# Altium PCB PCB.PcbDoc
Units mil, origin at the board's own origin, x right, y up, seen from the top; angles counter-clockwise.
Board outline 1000 x 650 mil, 2 copper layers (Top Layer, Bottom Layer), stack 62 mil thick; 20 components, 14 nets, 57 pads, 2 vias.
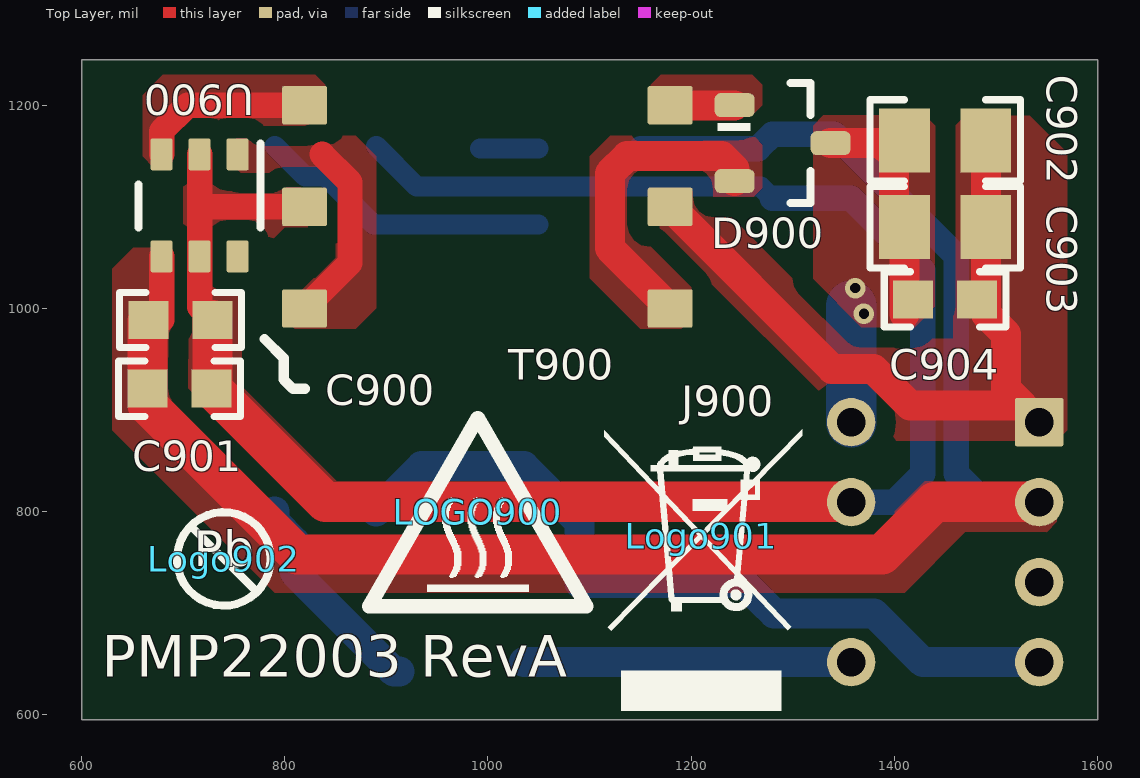
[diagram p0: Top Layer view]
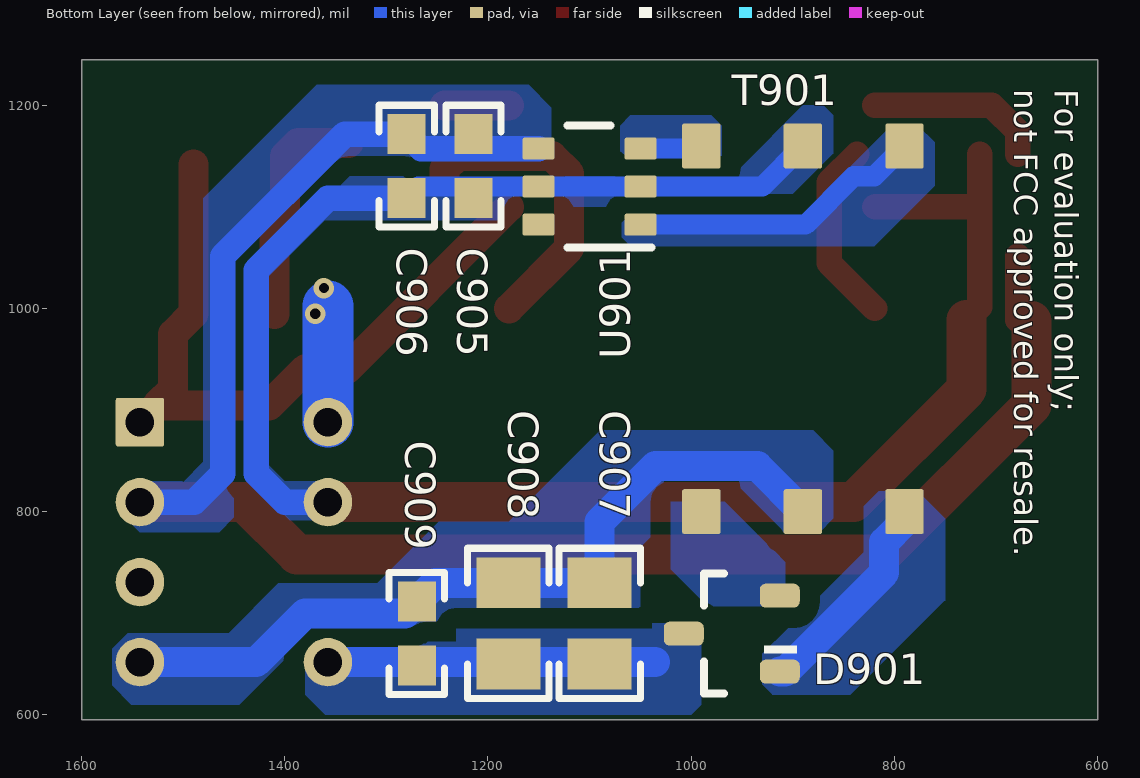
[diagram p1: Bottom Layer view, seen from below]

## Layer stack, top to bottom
Top Solder: solder mask 0.4, Solder Resist, Dk 3.5
Top Layer: signal copper 1.4
Dielectric 2: core 59.2, FR-4, Dk 4.2
Bottom Layer: signal copper 1.4
Bottom Solder: solder mask 0.4, Solder Resist, Dk 3.5

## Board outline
600,595 1600,595 1600,1245 600,1245

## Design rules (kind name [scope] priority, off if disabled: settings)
AcuteAngle [All] p1: minimum=4.50000000000000E+0001 checktracksonly=FALSE
AssemblyTestPointUsage [All] p1: valid=2
Clearance Clearance_2 [InNetClass('HV') vs Not InNetClass('HV')] p1: gap=50 ignorepadtopadclearanceinfootprint=FALSE except(0: Arc-Hole Track-Hole SMDPad-Hole THPad-Hole Via-Hole Fill-Hole Poly-Hole Region-Hole Text-Hole)
Clearance Clearance_1 [InNetClass('MV') vs Not InNetClass('MV')] p2: gap=20 ignorepadtopadclearanceinfootprint=FALSE
Clearance Clearance_Keepouts [((IsTrack Or IsArc) And Not InPoly) And IsFree and IsKeepOut vs ((IsTrack Or IsArc) And Not InPoly) And IsFree and IsKeepOut] p3: gap=0 ignorepadtopadclearanceinfootprint=FALSE
Clearance Clearance_BoardEdge_MountingHoles [OnCopper and InComponentClass('Mounting Holes') vs IsKeepOut] p4: gap=40 ignorepadtopadclearanceinfootprint=FALSE except(0: Arc-Hole Track-Hole SMDPad-Hole THPad-Hole Via-Hole Fill-Hole Poly-Hole Region-Hole Text-Hole)
Clearance Clearance_BoardEdge_Poly [OnCopper and InPoly vs IsKeepOut] p5: gap=25 ignorepadtopadclearanceinfootprint=FALSE except(0: Arc-Hole Track-Hole SMDPad-Hole THPad-Hole Via-Hole Fill-Hole Poly-Hole Region-Hole Text-Hole)
Clearance Clearance_BoardEdge [OnCopper and Not InComponentClass('Logo') and not InComponentClass('FiducialMark') and not InRegion(1000,500,4000,800) and Not IsKeepout vs IsKeepOut] p6: gap=75 ignorepadtopadclearanceinfootprint=FALSE except(0: Arc-Hole Track-Hole SMDPad-Hole THPad-Hole Via-Hole Fill-Hole Poly-Hole Region-Hole Text-Hole)
Clearance Clearance_Poly [InPolygon] p7: gap=20 ignorepadtopadclearanceinfootprint=FALSE except(0: Arc-Hole Track-Hole SMDPad-Hole THPad-Hole Via-Hole Fill-Hole Poly-Hole Region-Hole Text-Hole)
Clearance [All] p8: gap=7.87 ignorepadtopadclearanceinfootprint=FALSE except(0: Arc-Hole Track-Hole SMDPad-Hole THPad-Hole Via-Hole Fill-Hole Poly-Hole Region-Hole Text-Hole)
ComponentClearance ComponentClearance_MountingHoles_FiducialMarks [InComponentClass('Mounting Holes') vs InComponentClass('FiducialMark')] p1: gap=20 collisioncheckmode=3 verticalgap=10 showdistances=FALSE
ComponentClearance ComponentClearance_Shunt [InComponentClass('Header') vs InComponentClass('Shunt')] p2: gap=0 collisioncheckmode=3 verticalgap=0 showdistances=FALSE
ComponentClearance ComponentClearance_Logo [InComponentClass('Logo')] p3: gap=5 collisioncheckmode=3 verticalgap=10 showdistances=FALSE
ComponentClearance ComponentClearance_ScrewToNut [(HasFootprint('NY PMS 440 0025 PH')) vs (HasFootprint('Keystone_1902C'))] p4: gap=20 collisioncheckmode=3 verticalgap=100000 showdistances=FALSE
ComponentClearance ComponentClearance_MountingHoles [InComponentClass('Mounting Holes')] p5: gap=20 collisioncheckmode=3 verticalgap=10 showdistances=FALSE
ComponentClearance ComponentClearance_SmallPassives [HasFootprint('0201*') or HasFootprint('0402*') or HasFootprint('0508') or HasFootprint('0603*') or HasFootprint('0612') or HasFootprint('0805*') or HasFootprint('0815*') or HasFootprint('0830*') or HasFootprint('1206*') or HasFootprint('1210*') or HasFootprint('1808*') or HasFootprint('1812*') or HasFootprint('1825*') or HasFootprint('2010*') or HasFootprint('2220*') or HasFootprint('2225*') or HasFootprint('2512*') or HasFootprint('2728*') or HasFootprint('3518*') vs HasFootprint('0201*') or HasFootprint('0402*') or HasFootprint('0508') or HasFootprint('0603*') or HasFootprint('0612') or HasFootprint('0805*') or HasFootprint('0815*') or HasFootprint('0830*') or HasFootprint('1206*') or HasFootprint('1210*') or HasFootprint('1808*') or HasFootprint('1812*') or HasFootprint('1825*') or HasFootprint('2010*') or HasFootprint('2220*') or HasFootprint('2225*') or HasFootprint('2512*') or HasFootprint('2728*') or HasFootprint('3518*')] p6: gap=20 collisioncheckmode=3 verticalgap=20 showdistances=FALSE
ComponentClearance ComponentClearance_THtoSMT [IsThruComponent vs IsSMTComponent] p7: gap=10 collisioncheckmode=3 verticalgap=10 showdistances=FALSE
ComponentClearance ComponentClearance_THtoTH [IsThruComponent vs IsThruComponent] p8: gap=10 collisioncheckmode=3 verticalgap=10 showdistances=FALSE
ComponentClearance [All] p9: gap=10 collisioncheckmode=3 verticalgap=10 showdistances=FALSE
DiffPairsRouting [All] p1: maxlimit=100 minlimit=10 mostfreqgap=10 toplayer_minwidth=15 toplayer_maxwidth=15 toplayer_prefwidth=15 bottomlayer_minwidth=15 bottomlayer_maxwidth=15 bottomlayer_prefwidth=15 maxuncoupledlength=1000
FabricationTestPointUsage TestPointUsage [All] p1: valid=2 allowmultiple=FALSE
FabricationTestpoint Testpoint [All] p1: side=3 testpointundercomponent=TRUE minsize=40 maxsize=100 preferedsize=60 minholesize=0 maxholesize=40 preferedholesize=32 testpointgrid=1 allowsidetop=TRUE allowsidebottom=TRUE usegrid=TRUE gridtolerance=0.01
FanoutControl Fanout_LCC [IsLCC] p1: bgadir=Out bgaviamode=Centered fanoutstyle=Auto fanoutdirection=Alternating viagrid=1 // Fanout_LCC (Default Rule)
FanoutControl Fanout_BGA [IsBGA] p2: bgadir=Out bgaviamode=Centered fanoutstyle=Auto fanoutdirection=Alternating viagrid=1 // Fanout_BGA (Default Rule)
FanoutControl Fanout_Default [All] p4: bgadir=Out bgaviamode=Centered fanoutstyle=Auto fanoutdirection=Alternating viagrid=1 // Fanout_Default (Default Rule)
FanoutControl Fanout_Small [(CompPinCount < 5)] p5: bgadir=Out bgaviamode=Centered fanoutstyle=Auto fanoutdirection=OutThenIn viagrid=1 // Fanout_Small (Default Rule)
Height [All] p1: minheight=0 maxheight=3000 prefheight=500
HoleSize [All] p1: absolutevalues=TRUE maxlimit=251 minlimit=7 maxpercent=80.000 minpercent=20.000
MinimumAnnularRing MinimumAnnularRing_ThermalPadVias [IsVia and InAnyComponent] p1: minimumring=5.91
MinimumAnnularRing [All] p2: minimumring=4.9
MinimumSolderMaskSliver MinimumSolderMaskSliver_Logo [InComponentClass('Logo') vs InComponentClass('Logo')] p1: minsoldermaskwidth=0.7
MinimumSolderMaskSliver [All] p2: minsoldermaskwidth=2
PlaneConnect [All] p1: planeconnectstyle=Direct reliefexpansion=10 reliefentries=4 reliefconductorwidth=10 reliefairgap=10
PolygonConnect PolygonConnect_22 [All vs IsNamedPolygon('GND') Or  IsNamedPolygon('T901_1') Or  IsNamedPolygon('D901_1') Or  IsNamedPolygon('+VB') Or  IsNamedPolygon('T900_1') Or  IsNamedPolygon('-VB') Or  IsNamedPolygon('D900_2') Or  IsNamedPolygon('5V') Or  IsNamedPolygon('T901_3') Or  IsNamedPolygon('GND') Or  IsNamedPolygon('-VA') Or  IsNamedPolygon('D900_1') Or  IsNamedPolygon('5V') Or  IsNamedPolygon('T900_3') Or  IsNamedPolygon('D901_1') Or  IsNamedPolygon('+VA')] p1: connectstyle=Direct reliefconductorwidth=10 reliefentries=4 polygonreliefangle="90 Angle" airgapwidth=10
PolygonConnect PolygonConnect_21 [All vs IsNamedPolygon('GND') Or  IsNamedPolygon('+VA') Or  IsNamedPolygon('GND') Or  IsNamedPolygon('T900_3') Or  IsNamedPolygon('-VA') Or  IsNamedPolygon('D900_1') Or  IsNamedPolygon('D900_2') Or  IsNamedPolygon('5V') Or  IsNamedPolygon('T900_1') Or  IsNamedPolygon('5V')] p2: connectstyle=Direct reliefconductorwidth=10 reliefentries=4 polygonreliefangle="90 Angle" airgapwidth=10
PolygonConnect PolygonConnect_20 [All vs IsNamedPolygon('GND') Or  IsNamedPolygon('D900_1') Or  IsNamedPolygon('D900_2') Or  IsNamedPolygon('+VA') Or  IsNamedPolygon('-VA') Or  IsNamedPolygon('T900_1') Or  IsNamedPolygon('T900_3') Or  IsNamedPolygon('5V')] p3: connectstyle=Direct reliefconductorwidth=10 reliefentries=4 polygonreliefangle="90 Angle" airgapwidth=10
PolygonConnect PolygonConnect_19 [All vs IsNamedPolygon('GND') Or  IsNamedPolygon('T900_3') Or  IsNamedPolygon('T900_1') Or  IsNamedPolygon('5V')] p4: connectstyle=Direct reliefconductorwidth=10 reliefentries=4 polygonreliefangle="90 Angle" airgapwidth=10
PolygonConnect PolygonConnect_18 [All vs IsNamedPolygon('T900_1') Or  IsNamedPolygon('T900_3')] p5: connectstyle=Direct reliefconductorwidth=10 reliefentries=4 polygonreliefangle="90 Angle" airgapwidth=10
PolygonConnect PolygonConnect_17 [All vs IsNamedPolygon('4Vb') Or  IsNamedPolygon('4Va') Or  IsNamedPolygon('Comb') Or  IsNamedPolygon('PGND') Or  IsNamedPolygon('5Vp') Or  IsNamedPolygon('Comb') Or  IsNamedPolygon('Coma') Or  IsNamedPolygon('4Vb') Or  IsNamedPolygon('15Vb') Or  IsNamedPolygon('Coma') Or  IsNamedPolygon('15Va') Or  IsNamedPolygon('Comb') Or  IsNamedPolygon('Coma') Or  IsNamedPolygon('Comb') Or  IsNamedPolygon('4Vb') Or  IsNamedPolygon('15Vb') Or  IsNamedPolygon('15Va') Or  IsNamedPolygon('4Vb') Or  IsNamedPolygon('Coma') Or  IsNamedPolygon('4Va') Or  IsNamedPolygon('4Va') Or  IsNamedPolygon('4Va')] p6: connectstyle=Direct reliefconductorwidth=10 reliefentries=4 polygonreliefangle="90 Angle" airgapwidth=10
PolygonConnect PolygonConnect_16 [All vs IsNamedPolygon('15Va') Or  IsNamedPolygon('Coma') Or  IsNamedPolygon('4Vb') Or  IsNamedPolygon('Comb') Or  IsNamedPolygon('PGND') Or  IsNamedPolygon('15Vb') Or  IsNamedPolygon('4Va') Or  IsNamedPolygon('5Vp')] p7: connectstyle=Direct reliefconductorwidth=10 reliefentries=4 polygonreliefangle="90 Angle" airgapwidth=10
PolygonConnect PolygonConnect_15 [All vs IsNamedPolygon('C109_2') Or  IsNamedPolygon('C107_2') Or  IsNamedPolygon('HV') Or  IsNamedPolygon('Q203_5') Or  IsNamedPolygon('C107_2') Or  IsNamedPolygon('HS') Or  IsNamedPolygon('Q201_5') Or  IsNamedPolygon('Q203_5') Or  IsNamedPolygon('C106_2') Or  IsNamedPolygon('C108_2') Or  IsNamedPolygon('Vout') Or  IsNamedPolygon('Q203_5') Or  IsNamedPolygon('C108_2') Or  IsNamedPolygon('C113_2') Or  IsNamedPolygon('Q203_5') Or  IsNamedPolygon('Q201_5') Or  IsNamedPolygon('C107_2') Or  IsNamedPolygon('C102_1') Or  IsNamedPolygon('SGND') Or  IsNamedPolygon('GND') Or  IsNamedPolygon('SGND') Or  IsNamedPolygon('GND') Or  IsNamedPolygon('IN+') Or  IsNamedPolygon('IN+') Or  IsNamedPolygon('Q201_5') Or  IsNamedPolygon('Q201_5') Or  IsNamedPolygon('SGND') Or  IsNamedPolygon('SGND') Or  IsNamedPolygon('Vout') Or  IsNamedPolygon('Vout') Or  IsNamedPolygon('IN+') Or  IsNamedPolygon('GND') Or  IsNamedPolygon('IN+') Or  IsNamedPolygon('GND')] p8: connectstyle=Direct reliefconductorwidth=10 reliefentries=4 polygonreliefangle="90 Angle" airgapwidth=10
PolygonConnect PolygonConnect_14 [All vs IsNamedPolygon('C106_2') Or  IsNamedPolygon('C107_2') Or  IsNamedPolygon('C107_2') Or  IsNamedPolygon('C107_2') Or  IsNamedPolygon('C102_1') Or  IsNamedPolygon('Q203_5') Or  IsNamedPolygon('Vout') Or  IsNamedPolygon('Q203_5') Or  IsNamedPolygon('Q203_5') Or  IsNamedPolygon('Q201_5') Or  IsNamedPolygon('C108_2') Or  IsNamedPolygon('Q203_5') Or  IsNamedPolygon('HS') Or  IsNamedPolygon('HV') Or  IsNamedPolygon('C108_2') Or  IsNamedPolygon('Q201_5') Or  IsNamedPolygon('C109_2') Or  IsNamedPolygon('Q201_5') Or  IsNamedPolygon('Q201_5') Or  IsNamedPolygon('C113_2')] p9: connectstyle=Direct reliefconductorwidth=10 reliefentries=4 polygonreliefangle="90 Angle" airgapwidth=10
PolygonConnect PolygonConnect_13 [All vs IsNamedPolygon('C102_1') Or  IsNamedPolygon('HV') Or  IsNamedPolygon('C107_2') Or  IsNamedPolygon('C109_2') Or  IsNamedPolygon('C107_2') Or  IsNamedPolygon('C108_2') Or  IsNamedPolygon('C106_2') Or  IsNamedPolygon('C108_2') Or  IsNamedPolygon('C113_2') Or  IsNamedPolygon('C107_2')] p10: connectstyle=Direct reliefconductorwidth=10 reliefentries=4 polygonreliefangle="90 Angle" airgapwidth=10
PolygonConnect PolygonConnect_12 [All vs IsNamedPolygon('C107_2') Or  IsNamedPolygon('C113_2') Or  IsNamedPolygon('C106_2') Or  IsNamedPolygon('C107_2') Or  IsNamedPolygon('C107_2') Or  IsNamedPolygon('C102_1')] p11: connectstyle=Direct reliefconductorwidth=10 reliefentries=4 polygonreliefangle="90 Angle" airgapwidth=10
PolygonConnect PolygonConnect_11 [All vs IsNamedPolygon('C106_2') Or  IsNamedPolygon('C102_1') Or  IsNamedPolygon('C107_2') Or  IsNamedPolygon('C107_2') Or  IsNamedPolygon('C107_2')] p12: connectstyle=Direct reliefconductorwidth=10 reliefentries=4 polygonreliefangle="90 Angle" airgapwidth=10
PolygonConnect PolygonConnect_10 [All vs IsNamedPolygon('C106_2')] p13: connectstyle=Direct reliefconductorwidth=10 reliefentries=4 polygonreliefangle="90 Angle" airgapwidth=10
PolygonConnect PolygonConnect_9 [All vs IsNamedPolygon('C11_1') Or  IsNamedPolygon('Vin') Or  IsNamedPolygon('Vin') Or  IsNamedPolygon('5V') Or  IsNamedPolygon('D6_2') Or  IsNamedPolygon('Q3_3') Or  IsNamedPolygon('GND2') Or  IsNamedPolygon('GND2') Or  IsNamedPolygon('GND') Or  IsNamedPolygon('Q3_4') Or  IsNamedPolygon('12V5') Or  IsNamedPolygon('GND') Or  IsNamedPolygon('12V5') Or  IsNamedPolygon('D3_1')] p14: connectstyle=Direct reliefconductorwidth=10 reliefentries=4 polygonreliefangle="90 Angle" airgapwidth=10
PolygonConnect PolygonConnect_8 [All vs IsNamedPolygon('C11_1') Or  IsNamedPolygon('Vin') Or  IsNamedPolygon('12V5') Or  IsNamedPolygon('Q3_3') Or  IsNamedPolygon('GND2') Or  IsNamedPolygon('GND2') Or  IsNamedPolygon('5V') Or  IsNamedPolygon('Q3_4') Or  IsNamedPolygon('12V5')] p15: connectstyle=Direct reliefconductorwidth=10 reliefentries=4 polygonreliefangle="90 Angle" airgapwidth=10
PolygonConnect PolygonConnect_7 [All vs IsNamedPolygon('GND2') Or  IsNamedPolygon('GND2') Or  IsNamedPolygon('5V') Or  IsNamedPolygon('12V5') Or  IsNamedPolygon('12V5') Or  IsNamedPolygon('C11_1')] p16: connectstyle=Direct reliefconductorwidth=10 reliefentries=4 polygonreliefangle="90 Angle" airgapwidth=10
PolygonConnect PolygonConnect_6 [All vs IsNamedPolygon('GND2') Or  IsNamedPolygon('SGND') Or  IsNamedPolygon('GND1') Or  IsNamedPolygon('C901_1') Or  IsNamedPolygon('SGND') Or  IsNamedPolygon('GND2') Or  IsNamedPolygon('GND1')] p17: connectstyle=Direct reliefconductorwidth=10 reliefentries=4 polygonreliefangle="90 Angle" airgapwidth=10
PolygonConnect PolygonConnect_5 [All vs IsNamedPolygon('GND1') Or  IsNamedPolygon('GND1')] p18: connectstyle=Direct reliefconductorwidth=10 reliefentries=4 polygonreliefangle="90 Angle" airgapwidth=10
PolygonConnect PolygonConnect_4 [All vs IsNamedPolygon('C21_1') Or  IsNamedPolygon('C5_1') Or  IsNamedPolygon('C12_2') Or  IsNamedPolygon('C2_2') Or  IsNamedPolygon('C13_1') Or  IsNamedPolygon('C28_1') Or  IsNamedPolygon('C6_1') Or  IsNamedPolygon('GND') Or  IsNamedPolygon('GND2') Or  IsNamedPolygon('C14_1') Or  IsNamedPolygon('C13_1') Or  IsNamedPolygon('Q1_3') Or  IsNamedPolygon('C14_1') Or  IsNamedPolygon('C5_1') Or  IsNamedPolygon('GND2') Or  IsNamedPolygon('C28_1') Or  IsNamedPolygon('D5_2') Or  IsNamedPolygon('D6_2') Or  IsNamedPolygon('D2_1') Or  IsNamedPolygon('C12_2') Or  IsNamedPolygon('D2_1') Or  IsNamedPolygon('C4_1') Or  IsNamedPolygon('C4_1') Or  IsNamedPolygon('C2_2') Or  IsNamedPolygon('GND') Or  IsNamedPolygon('C33_1') Or  IsNamedPolygon('C9_1')] p19: connectstyle=Direct reliefconductorwidth=10 reliefentries=4 polygonreliefangle="90 Angle" airgapwidth=10
PolygonConnect PolygonConnect_3 [All vs IsNamedPolygon('C28_1') Or  IsNamedPolygon('C12_2') Or  IsNamedPolygon('C28_1') Or  IsNamedPolygon('C9_1') Or  IsNamedPolygon('D5_2') Or  IsNamedPolygon('C12_2') Or  IsNamedPolygon('C2_2') Or  IsNamedPolygon('C14_1') Or  IsNamedPolygon('C4_1') Or  IsNamedPolygon('C14_1') Or  IsNamedPolygon('D6_2') Or  IsNamedPolygon('GND2') Or  IsNamedPolygon('Q1_3') Or  IsNamedPolygon('C5_1') Or  IsNamedPolygon('D2_1') Or  IsNamedPolygon('C4_1') Or  IsNamedPolygon('C13_1') Or  IsNamedPolygon('C5_1') Or  IsNamedPolygon('C13_1') Or  IsNamedPolygon('C33_1') Or  IsNamedPolygon('D2_1') Or  IsNamedPolygon('GND') Or  IsNamedPolygon('GND') Or  IsNamedPolygon('GND2') Or  IsNamedPolygon('C2_2') Or  IsNamedPolygon('C6_1') Or  IsNamedPolygon('C21_1')] p20: connectstyle=Direct reliefconductorwidth=10 reliefentries=4 polygonreliefangle="90 Angle" airgapwidth=10
PolygonConnect PolygonConnect_2 [All vs IsNamedPolygon('C21_1') Or  IsNamedPolygon('C4_1') Or  IsNamedPolygon('D5_2') Or  IsNamedPolygon('C5_1') Or  IsNamedPolygon('C14_1') Or  IsNamedPolygon('C13_1') Or  IsNamedPolygon('C4_1') Or  IsNamedPolygon('C33_1') Or  IsNamedPolygon('C12_2') Or  IsNamedPolygon('D2_1') Or  IsNamedPolygon('C2_2') Or  IsNamedPolygon('C28_1') Or  IsNamedPolygon('C12_2') Or  IsNamedPolygon('D2_1') Or  IsNamedPolygon('C5_1') Or  IsNamedPolygon('Q1_3') Or  IsNamedPolygon('GND') Or  IsNamedPolygon('D6_2') Or  IsNamedPolygon('C6_1') Or  IsNamedPolygon('C2_2') Or  IsNamedPolygon('C14_1') Or  IsNamedPolygon('C28_1') Or  IsNamedPolygon('C13_1') Or  IsNamedPolygon('C9_1') Or  IsNamedPolygon('GND')] p21: connectstyle=Direct reliefconductorwidth=10 reliefentries=4 polygonreliefangle="90 Angle" airgapwidth=10
PolygonConnect PolygonConnect_1 [All vs IsNamedPolygon('C28_1') Or  IsNamedPolygon('D5_2') Or  IsNamedPolygon('C5_1') Or  IsNamedPolygon('C5_1') Or  IsNamedPolygon('D2_1') Or  IsNamedPolygon('C21_1') Or  IsNamedPolygon('C9_1') Or  IsNamedPolygon('C4_1') Or  IsNamedPolygon('C14_1') Or  IsNamedPolygon('C28_1') Or  IsNamedPolygon('C6_1') Or  IsNamedPolygon('C12_2') Or  IsNamedPolygon('C33_1') Or  IsNamedPolygon('C4_1') Or  IsNamedPolygon('C13_1') Or  IsNamedPolygon('C12_2') Or  IsNamedPolygon('D6_2') Or  IsNamedPolygon('C2_2') Or  IsNamedPolygon('C14_1') Or  IsNamedPolygon('D2_1') Or  IsNamedPolygon('C2_2') Or  IsNamedPolygon('C13_1')] p22: connectstyle=Direct reliefconductorwidth=10 reliefentries=4 polygonreliefangle="90 Angle" airgapwidth=10
PolygonConnect [All] p23: connectstyle=Relief reliefconductorwidth=10 reliefentries=4 polygonreliefangle="90 Angle" airgapwidth=10
RoutingVias ThermalPadVias [IsVia and InAnyComponent] p1: holewidth=7.87 width=19.68 viastyle="Through Hole" minholewidth=7.87 minwidth=19.68 maxholewidth=12.99 maxwidth=23.62
RoutingVias [All] p2: holewidth=16 width=34 viastyle="Through Hole" minholewidth=7.87 minwidth=20 maxholewidth=40 maxwidth=65
SilkToBoardRegionClearance [Not ((IsComment or IsDesignator) And (Hide <> 'False')) and not InRegion(1000,500,4000,800)] p1:
SilkToSilkClearance SilkToSilkClearance_Pb-FreeLogo [(HasFootprint('Pb-Free_Overlay_Medium') OR HasFootprint('Pb-Free_Overlay_Small')) vs (HasFootprint('Pb-Free_Overlay_Medium') OR HasFootprint('Pb-Free_Overlay_Small'))] p1: silktosilkclearance=0
SilkToSilkClearance [All] p2: silktosilkclearance=1
SilkToSolderMaskClearance "Silk to Solder Mask Opening" [All] p1: minsilkscreentomaskgap=1 clearancetoexposedcopper=FALSE
SolderMaskExpansion [All] p1: expansion=1.97
Width [All] p1: maxlimit=100 minlimit=6 preferedwidth=10 checkconnectedcopper=TRUE
14 further rules are at their usual default settings.

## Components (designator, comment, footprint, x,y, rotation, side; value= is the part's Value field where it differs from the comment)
C900 "C1608X6S1A106M080AC" 0603 697.45,988.7 r180 top value=10uF
C901 "CGA3E2X7R1E104K080AA" 0603 696.46,921 r180 top value=0.1uF
C902 "CGA4J3X5R1H475K125AB" 0805_HV 1450,1165.49 r0 top value=4.7uF
C903 "CGA4J3X5R1H475K125AB" 0805_HV 1450,1080 r0 top value=4.7uF
C904 "CGA3E2X7R1E104K080AA" 0603 1450,1008.88 r0 top value=0.1uF
C905 "C1608X6S1A106M080AC" 0603 1214.21,1140 r90 bottom value=10uF
C906 "CGA3E2X7R1E104K080AA" 0603 1280,1140 r90 bottom value=0.1uF
C907 "CGA4J3X5R1H475K125AB" 0805_HV 1090,690 r90 bottom value=4.7uF
C908 "CGA4J3X5R1H475K125AB" 0805_HV 1180,690 r90 bottom value=4.7uF
C909 "CGA3E2X7R1E104K080AA" 0603 1270,680 r90 bottom value=0.1uF
D900 "BAV70-E3-08" SOT-23 1290,1162.8 r0 top value=70V
D901 "BAV70-E3-08" SOT-23 960,680 r0 bottom value=70V
J900 "MMS-104-01-F-DH" FP-MMS-104-01-F-DH_HDR8-MFG 1450,770 r90 top
LOGO900 "CAUTION HOT SURFACE" IEC_HotSurface_Small 990,800 r0 top
Logo901 "WEEE logo" WEEE_Minimum 1210,776.5 r0 top
Logo902 "Pb-Free Symbol" Pb-Free_Overlay_Small 740,753.5 r0 top
T900 "750317722" Wurth_750317722 999.37,1100 r0 top
T901 "750317722" Wurth_750317722 890,980 r270 bottom
U900 "SN6505BDBVR" DBV0006A_L 716.15,1101.5 r270 top
U901 "SN6505BDBVR" DBV0006A_L 1100,1120 r0 bottom

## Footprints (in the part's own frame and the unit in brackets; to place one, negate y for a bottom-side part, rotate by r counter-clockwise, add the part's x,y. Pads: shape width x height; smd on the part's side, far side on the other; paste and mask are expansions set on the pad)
0603 [mm] "0603 from SM-752 data"
  rect 1x0.95 smd: 1(-0.8,0) 2(0.8,0)
  silkscreen extent -1.52,-0.69 1.52,0.69, body extent -0.87,-0.47 0.87,0.47, height 1
0805_HV [mil] "0805 with 30mil clearance between pads"
  rect 50x63 smd: 1(-40,0) 2(40,0)
  silkscreen extent -74,-40 74,40, body extent -43,-29 43,29, height 57
DBV0006A_L [mm] "SOT23, 6-Leads, Body 2.9x1.6mm, Pitch 0.95mm, Lead Span 2.8mm, IPC High Density"
  rrect18% 0.8x0.55 smd: 1(-1.275,0.95) 2(-1.275,0) 3(-1.275,-0.95) 4(1.275,-0.95) 5(1.275,0) 6(1.275,0.95)
  silkscreen extent -1.55,-1.53 0.55,1.53, body extent -1.42,-1.46 1.42,1.46, height 1.12
FP-MMS-104-01-F-DH_HDR8-MFG [mm]
  rrect8% 1.211x1.211 hole 0.711 paste-1000 mask+0: 1(3,-2.35)
  round 1.211 hole 0.711 paste-1000 mask+0: 2(3,2.35) 3(1,-2.35) 4(1,2.35) 5(-1,-2.35) 7(-3,-2.35) 8(-3,2.35)
  body extent -4.44,-3.06 4.44,3.06, height 0.25
IEC_HotSurface_Small [mil]
  silkscreen extent -107,-93 107,92
Pb-Free_Overlay_Small [mil]
  silkscreen extent -46,-46 46,46
SOT-23 [mm] "SOT23, 3-Leads, Body 2.9x1.3mm, Pitch 0.95mm, Lead Span 2.5mm, IPC Medium Density"
  rrect50% 1x0.6 smd: 1(-1.2,0.95) 2(-1.2,-0.95) 3(1.2,0)
  silkscreen extent -1.63,-1.5 0.7,1.5, body extent -1.16,-1.45 1.21,1.45, height 1
WEEE_Minimum [mil] "WEEElie bin"
  silkscreen extent -95,-172 99,104
Wurth_750317722 [mm] "SMD, 6-Leads, Body 7.14x6.73mm, Pitch 2.54mm"
  rrect10% 1.12x0.96 smd: 1(-4.57,2.54) 2(-4.57,0) 3(-4.57,-2.54) 4(4.57,-2.54) 5(4.57,0) 6(4.57,2.54)
  body extent -5.23,-3.36 5.23,3.37, height 4.19

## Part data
C900 C905: library part GRT188C81A106ME13D, "CAP, CERM, 10 µF, 10 V,+/- 20%, X6S, AEC-Q200 Grade 2, 0603", Cap_Case=0603, Manufacturer=TDK, TempCo=X6S, Tolerance_%=20, Value2=10V, ValueDisplayed=10µF
C901 C904 C906 C909: "CAP, CERM, 0.1 µF, 25 V,+/- 10%, X7R, AEC-Q200 Grade 1, 0603", Cap_Case=0603, Manufacturer=TDK, Supplier Part Number 1=445-5667-1-ND, TempCo=X7R, Tolerance_%=10, Value2=25V, ValueDisplayed=0.1µF
C902 C903 C907 C908: library part GRT21BR61H475KE13L, "CAP, CERM, 4.7 µF, 50 V,+/- 10%, X5R, AEC-Q200 Grade 3, 0805", Cap_Case=0805, Manufacturer=TDK, TempCo=X5R, Tolerance_%=10, Value2=50V, ValueDisplayed=4.7µF
D900 D901: "Diode, Switching, 70 V, 0.25 A, AEC-Q101, SOT-23", Manufacturer=Vishay-Semiconductor, Supplier Part Number 1=BAV70-E3-08CT-ND, Value1=0.25A, Value2=1.25V
J900: library part CMP-0087213-1, "8 Position Receptacle Connector Through Hole, Right Angle", Current_A=3.9A, Manufacturer=Samtec, Voltage_V=350V
LOGO900: library part IEC_HotSurface, "IEC 61010-1 Hot Surface Warning"
Logo901: library part CMP-0074769-1
Logo902: library part CMP-0074839-1
T900 T901: library part CMP-0081994-1, "Transformer, 320 uH, SMD", Manufacturer="Wurth Elektronik"
U900 U901: library part CMP-0076095-1, "Low-Noise 1 A, 420 kHz Transformer Driver, DBV0006A (SOT-23-6)", Alternate Manufacturer="Texas Instruments", Alternate PartNumber=SN6505BDBVT

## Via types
v1: diameter 20, hole 10, Top Layer to Bottom Layer, 2 vias

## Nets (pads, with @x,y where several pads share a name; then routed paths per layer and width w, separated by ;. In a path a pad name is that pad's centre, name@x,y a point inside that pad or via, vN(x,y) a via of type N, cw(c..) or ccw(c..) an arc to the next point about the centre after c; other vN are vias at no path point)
5V: C900.1 C901.1 C905.1 C906.1 J900.4 T900.2 T901.2 U900.2 U900.5 U901.2 U901.5 | length 1884.1
  Top Layer w25: U900.2 U900.5 716.15,1001.5 C900.1 ; 717.64,1100 T900.2
  Top Layer w39.37: C900.1 728.94,920.62 840.2,809.37 J900.4
  Bottom Layer w20: T901.2 929.92,1120 U901.2 U901.5 1268.5,1120 C906.1
  Bottom Layer w25: C906.1 1357.5,1108.5 1428.11,1037.89 1428.11,837.48 1400,809.37 J900.4
+VA: C902.1 C903.1 C904.1 D900.3 J900.2 | length 341.8
  Top Layer w29.53: D900.3 1387.21,1162.8 1399.81,1150.21 1399.81,1090.19 C903.1 C904.1@1410,994.8
  Bottom Layer w50: J900.2 1357.48,1002.52
  other v1: 1370,994.8 1361.5,1020
+VB: C907.1 C908.1 C909.1 D901.3 J900.8 | length 322.1
  Bottom Layer w29.53: 1035.35,651.89 J900.8
-VA: C902.2 C903.2 C904.2 J900.1 T900.5 | length 679.5
  Top Layer w29.53: T900.5 1338.63,940.67 1379.33,940.67 1415.32,904.68 1525.95,904.68 1510,920.63 1510,974.8 1490,994.8 C903.2 C902.2@1490,1141.7
-VB: C907.2 C908.2 C909.2 J900.7 T901.5 | length 786.1
  Bottom Layer w29.53: T901.5 934.69,844.76 1035.24,844.76 1090,790 C907.2 C908.2 1251.5,730 C909.2 1281.5,700 1380,700 1428.11,651.89 J900.7
GND: C900.2 C901.2 C905.2 C906.2 J900.3 U900.4 U901.4 | length 1779.6
  Top Layer w25: C900.2@665.95,987.72 C900.2 ; C900.2@678.75,988.7 U900.4
  Top Layer w39.37: C900.2@664.97,987.72 C901.2 664.97,905.03 812.03,757.97 1387.97,757.97 1439.37,809.37 J900.3
  Bottom Layer w25: U901.4 1265.91,1157.4 C906.2 1340.99,1171.5 1460.98,1051.51 1460.98,837.48 1489.09,809.37 J900.3
NetD900_1: D900.1 T900.6 | length 63.3
  Top Layer w29.53: T900.6 D900.1@1242.55,1200
NetD900_2: D900.2 T900.4 | length 304.5
  Top Layer w29.53: T900.4 1120,1059.29 1120,1132.99 1137.01,1150 1230,1150 1242.76,1137.24 D900.2
NetD901_1: D901.1 T901.6 | length 211.5
  Bottom Layer w29.53: T901.6 790,790 810,770 810,740 907.4,642.6 D901.1
NetD901_2: D901.2 T901.4
NetT900_1: T900.1 U900.3 | length 174.1
  Top Layer w25: U900.3 678.75,1174.49 704.25,1200 T900.1
NetT900_3: T900.3 U900.1 | length 181.6
  Top Layer w25: T900.3 864.25,1044.8 864.25,1124.19 836.75,1151.69
NetT901_1: T901.1 U901.1 | length 291.8
  Bottom Layer w20: T901.1 819.92,1130 840,1130 887.4,1082.6 U901.1
NetT901_3: T901.3 U901.3 | length 57.3
  Bottom Layer w20: T901.3@992.52,1157.4 U901.3
pads on no net: J900.5 U900.6 U901.6

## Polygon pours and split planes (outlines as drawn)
NetT900_1 on Top Layer "T900_1" (solid, pour order 0): 690,1140 690,1160 710,1180 830,1180 840,1190 840,1220 830,1230 680,1230 660,1210 660,1149.78 670.7,1139.09
NetT900_3 on Top Layer "T900_3" (solid, pour order 2): 744.67,1160 754.67,1170 870,1170 890,1150 890,1000 870,980 810,980 800,990 800,1001.5 828.5,1030 830,1030 850,1050 850,1120 836.44,1133.56 756.83,1133.56 745.7,1144.7
5V on Top Layer "5V" (solid, pour order 4): 710,1157.52 702.26,1149.78 700,1149.78 700,910 820,790 1361.5,790 1361.5,820 1351.5,830 851,830 757.43,923.57 757.43,1037.43 800,1080 822.87,1080 822.87,1111.71 814.58,1120 757.52,1120 720,1157.52
GND on Top Layer "GND" (solid, pour order 6): 678.75,1059.78 650.93,1059.87 630,1038.94 630,880 790,720 1410,720 1470,780 1550,780 1560,790 1560,812.52 1542.52,830 1430,830 1380,780 822.3,780 690,912.3 690,1050
NetD900_1 on Top Layer "D900_1" (solid, pour order 8): 1160,1190 1160,1220 1170,1230 1260,1230 1270,1220 1270,1199.98 1269.98,1199.98 1260,1190
NetD900_2 on Top Layer "D900_2" (solid, pour order 10): 1190,980 1200,990 1200,1020.75 1150,1070.75 1150,1119.33 1160.67,1130 1194.21,1130 1214.21,1110 1261.5,1110 1270,1118.5 1270,1161.3 1261.3,1170 1120.22,1170 1100,1149.78 1100,1030 1150,980
+VA on Top Layer "+VA" (solid, pour order 12): 1330,1190 1320,1180 1320,1029.14 1367.46,981.68 1419.85,981.68 1440,1001.83 1440,1180 1430,1190
-VA on Top Layer "-VA" (solid, pour order 14): 1470,1189.93 1460,1179.93 1460,1001.89 1430.42,972.31 1357.04,972.31 1209.35,1120 1178.9,1120 1168.9,1110 1168.9,1075.35 1374.25,870 1560,870 1570,880 1570,1153.39 1533.47,1189.93
-VB on Bottom Layer "-VB" (solid, pour order 30): 873.57,779.92 860,793.5 860,860 880,880 1089.37,880 1179.37,790 1248.54,790 1309.03,729.51 1406.21,729.51 1455.2,680.52 1554.41,680.52 1570,664.94 1570,629 1551,610 1445,610 1375,680 1070,680 1050,700 1050,765.16 1035.24,779.92
NetD901_1 on Bottom Layer "D901_1" (solid, pour order 28): 777.01,820 750,792.99 750,712.4 750.83,712.4 843.23,620 920,620 920,620.08 929.92,630 929.92,659.94 830,759.86 830,805.58 815.58,820
NetD901_2 on Bottom Layer "D901_1" (solid, pour order 26): 1013.01,820 1020,813.01 1020,743.43 983.58,707 911.9,707 907.4,711.5 907.4,750.39 977.01,820
+VB on Bottom Layer "+VB" (solid, pour order 24): 990,690 990,610 1000,600 1360,600 1380,620 1380,660 1370,670 1261.3,670 1241.3,690
NetT901_1 on Bottom Layer "T901_1" (solid, pour order 22): 777.01,1180 760.46,1163.45 760.46,1120.61 820,1061.07 1059.55,1061.07 1068.48,1070 1068.48,1084.38 1062.41,1090.45 892.54,1090.45 802.99,1180
NetT901_3 on Bottom Layer "T901_3" (solid, pour order 20): 980,1190 970,1180 970,1147.01 977.01,1140 1060.13,1140 1070,1149.87 1070,1180 1060,1190
GND on Bottom Layer "GND" (solid, pour order 18): 1137.54,1150.69 1137.54,1197.54 1160,1220 1368.54,1220 1480,1108.54 1480,849 1500,829 1501,830 1550,830 1560,820 1560,797.48 1542.52,780 1464.65,780 1450,794.65 1450,1031.51 1341.51,1140 1149.92,1140 1139.92,1150
5V on Bottom Layer "5V" (solid, pour order 16): 870,1200 860,1190 860,1140 900,1100 1167.01,1100 1180,1087.01 1360.41,1087.01 1420,1027.42 1420,850 1400,830 1360,830 1350,820 1350,791.5 1395.32,791.5 1440,836.18 1440,1050 1360,1130 960,1130 890,1200

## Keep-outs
Keep-Out Layer:
  text ".Layer_Name" at 577,-858.49 h60

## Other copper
Top Layer:
  text ".Layer_Name" at 577,-858.49 h60
Bottom Layer:
  text ".Layer_Name" at 577,-858.49 h60

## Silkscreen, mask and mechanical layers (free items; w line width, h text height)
Top Overlay:
  lines w10: 780,970 799,951 799,930 808,921 820,921
  text "PMP22003 RevA" at 620,623.94 h70
  text ".Layer_Name" at 577,-858.49 h60
Bottom Overlay:
  text "For evaluation only;" at 650,1215.98 h40 r90
  text "not FCC approved for resale." at 690,1215.98 h40 r90
  text ".Layer_Name" at 577,-858.49 h60
Top Paste:
  text ".Layer_Name" at 577,-858.49 h60
Bottom Paste:
  text ".Layer_Name" at 577,-858.49 h60
Top Solder:
  text ".Layer_Name" at 577,-858.49 h60
  text ".Layer_Name" at 577,-858.49 h60
Bottom Solder:
  text ".Layer_Name" at 577,-858.49 h60
Drill Guide:
  text ".Layer_Name" at 577,-858.49 h60
M1 Board Outline:
  the board outline again, w10
  text ".Layer_Name" at 577,-858.49 h60
M2 Board Dimensions:
  rectangle: 0,-275 125,-150
  rectangle: 125,-400 500,-275
  lines w7: 0,-275 1000,-275 ; 125,-400 125,-150 ; 250,-400 250,-150 ; 500,-400 500,-150 ; 750,-400 750,-150 ; 0,-400 1000,-400 1000,-150 0,-150 0,-400
  text ".Layer_Name" at 577,-858.49 h60
M3 3D STEP Top:
  text ".Layer_Name" at 577,-858.49 h60
M4 3D STEP Bottom:
  text ".Layer_Name" at 577,-858.49 h60
M5 Assembly Top:
  lines w10: -292,-930.17 6308,-930.17 ; -292,-726.83 6310,-726.83 ; -292,-523.5 -292,-1133.5 3713,-1133.5 6310,-1133.5 6310,-523.5 -291.5,-523.5 -291.5,-1133.5 1284,-1133.5 ; 2173,-1133.5 2173,-523.5 ; 3440,-726.83 3440,-523.5 ; 4280,-726.83 4280,-523.5 ; 4902,-1140 4902,-937.17
  text "COMPONENTS MARKED 'DNP' SHOULD NOT BE POPULATED." at 1153.5,-318.5 h60
  text "ASSEMBLY VARIANT:" at 1153,-434 h60
  text ".VariantName" at 2189,-434 h60
  text "PCB VIEWED FROM TOP SIDE" at -228.5,-655.67 h60
  text "BOARD #:" at 2248,-655.67 h60
  text ".PRJ_Number" at 2793.5,-655.67 h60
  text "REV:" at 3638,-655.67 h60
  text ".PCB_Rev" at 3929.5,-655.67 h60
  text "SVN REV:" at 4476,-655.67 h60
  text ".VersionControl_RevNumber" at 4982,-655.67 h60
  text "TID #:" at 2248,-859 h60
  text ".TID" at 2793.5,-859 h60
  text "PLOT NAME =" at -228.5,-1064.34 h60
  text ".plot_File_Name" at 577,-1064.34 h60
  text "GENERATED    :" at 2250,-1064.34 h60
  text ".Print_Date" at 3119.5,-1064.34 h60
  text ".Print_Time" at 3848.5,-1064.34 h60
  text "TEXAS INSTRUMENTS" at 5113,-1064.34 h60
M6 Assembly Bottom:
  lines w10: -292.5,-727.33 6309.5,-727.33 ; -290.5,-930.67 6309.5,-930.67 ; 1115.5,-1140.5 1115.5,-937.67 ; 1737.5,-727.33 1737.5,-524 ; 2577.5,-727.33 2577.5,-524 ; 3844.5,-1134 3844.5,-524 ; 4733.5,-1134 6309,-1134 6309,-524 -292.5,-524 -292.5,-1134 2304.5,-1134 6309.5,-1134 6309.5,-524
  text "COMPONENTS MARKED 'DNP' SHOULD NOT BE POPULATED." at 6102,-318 h60
  text ".VariantName" at 5058,-434 h60
  text "ASSEMBLY VARIANT:" at 6097,-434 h60
  text ".VersionControl_RevNumber" at 1035.5,-656.17 h60
  text "SVN REV:" at 1541.5,-656.17 h60
  text ".PCB_Rev" at 2088,-656.17 h60
  text "REV:" at 2379.5,-656.17 h60
  text ".PRJ_Number" at 3224,-656.17 h60
  text "BOARD #:" at 3769.5,-656.17 h60
  text "PCB VIEWED FROM BOTTOM SIDE" at 6246,-656.17 h60
  text ".TID" at 3224,-859.5 h60
  text "TID #:" at 3769.5,-859.5 h60
  text "TEXAS INSTRUMENTS" at 904.5,-1064.84 h60
  text ".Print_Time" at 2169,-1064.84 h60
  text ".Print_Date" at 2898,-1064.84 h60
  text "GENERATED    :" at 3767.5,-1064.84 h60
  text ".plot_File_Name" at 5440.5,-1064.84 h60
  text "PLOT NAME =" at 6246,-1064.84 h60
M9 Title Sheet:
  drawing of 57 lines, arcs and shapes, not listed
  text "1" at 739.84,8036.5 h70
  text "2" at 3235.5,8036.5 h70
  text "3" at 5724.84,8036.5 h70
  text "4" at 8231.51,8036.5 h70
  text "5" at 10730.5,8036.5 h70
  text "6" at 13235.5,8036.5 h70
  text "A" at -416.5,6893.5 h70
  text "A" at 14383.5,6893.5 h70
  text "B" at -416.5,4513.5 h70
  text "B" at 14383.5,4513.5 h70
  text "C" at -416.5,2138.5 h70
  text "C" at 14383.5,2138.5 h70
  text "PROJECT TITLE:" at 11343.5,277.5 h45
  text ".PRJ_Title" at 11393.5,144.17 h70
  text "DESIGNED FOR:" at 11343.5,-23.5 h45
  text ".PRJ_Customer" at 11393.5,-163.5 h70
  text "D" at -416.5,-231.5 h70
  text "D" at 14383.5,-231.5 h70
  text "FILE NAME:" at 11343.5,-323.5 h45
  text ".PCB_File_Name_No_Path" at 11393.5,-443.5 h70
  text "Texas Instruments (TI) and/or its licensors do not warrant the accuracy or completeness of this specification" at 6374,-605.34 h45
  text "ENGINEER:" at 11343.5,-613.5 h45
  text "LAYOUT BY:" at 12848.5,-613.5 h45
  text "or any information contained therein. TI and/or its licensors do not warrant that this design will meet" at 6329.01,-718 h45
  text ".PRJ_Engineer" at 11393.5,-768.49 h70
  text ".PCB_Layout" at 12899,-768.49 h70
  text "the specifications, will be suitable for your application or fit for any particular purpose, or will operate in" at 6329.01,-830.67 h45
  text ".Layer_Name" at 577,-858.49 h60
  text "ALTIUM DESIGNER VERSION:" at 12848.5,-923.5 h45
  text "an implementation. TI and/or its licensors do not warrant that the design is production worthy. You should" at 6329.01,-943.33 h45
  text "completely validate and test your design implementation to confirm the system functionality for your application." at 6374,-1056 h45
  text ".print_Scale" at 11393.5,-1056.83 h70
  text ".Application_BuildNumber" at 12899,-1056.83 h70
  text "1" at 739.84,-1263.5 h70
  text "2" at 3235.5,-1263.5 h70
  text "3" at 5724.84,-1263.5 h70
  text "4" at 8231.51,-1263.5 h70
  text "5" at 10730.5,-1263.5 h70
  text "6" at 13235.5,-1263.5 h70
M10 Fab Notes:
  drawing of 189 lines, arcs and shapes, not listed
  text "DESIGN INFORMATION" at 12382.02,6356.17 h60
  text "MIN. TRACK WIDTH:" at 11737.46,6224.05 h60
  text "8" at 12833.7,6224.05 h60
  text "MIL" at 12988.46,6224.05 h60
  text "MIN. CLEARANCE:" at 11737.46,6099.92 h60
  text "0.2" at 12773.7,6099.93 h60
  text "mm" at 12988.46,6099.92 h60
  text "MIN. VIA PAD SIZE:" at 11737.46,5975.8 h60
  text "24" at 12803.71,5975.8 h60
  text "MIL" at 12988.46,5975.8 h60
  text "0.05mm (2MIL)" at 12432.46,5845.9 h60
  text "MINIMUM ANNULAR RING" at 11408.23,5837.67 h60
  text "EXTERNAL" at 13140.46,5837.67 h60
  text "PER" at 11608.23,5727.55 h60
  text "IPC-D-275 CLASS 2 LEVEL C" at 11828.23,5727.54 h60
  text "MIL, HOLES" at 13316.46,5627.07 h60
  text "+/-" at 12924,5618.48 h60
  text "+/-" at 13778,5618.48 h60
  text "REGISTRATION TOLERANCES:" at 11408.23,5617.42 h60
  text "METAL" at 12608,5617.42 h60
  text "5" at 13184.2,5617.42 h60
  text "3" at 14017.2,5617.42 h60
  text "MIL" at 14133.46,5617.42 h60
  text "HOLE SIZE TOLERANCE (UNLESS OTHERWISE SPECIFIED):" at 11408.23,5519.1 h60
  text "+/-" at 13778,5516.23 h60
  text "3" at 14017.2,5515.17 h60
  text "MIL" at 14133.46,5515.17 h60
  text "MATERIAL:" at 11333.46,5377.52 h60
  text "FR-4 High Tg" at 12319.9,5249 h60
  text "X" at 12175.46,5241.01 h60
  text "FR-408" at 11754.46,5236.49 h60
  text "OTHER" at 13242.46,5236.49 h60
  text "62 MIL (1.6mm) +/-10%" at 12074.56,5093.46 h60
  text "X" at 11954.46,5091.01 h60
  text "THICKNESS:" at 11408.23,5085.24 h60
  text "OTHER" at 13359.46,5085.24 h60
  text "TOLERANCE:" at 11408.23,4946.92 h60
  text "X" at 12256.46,4946.92 h60
  text "ANSI IPC-6012 TYPE 3 CLASS 2" at 12434.48,4946.92 h60
  text "OTHER +/-" at 12434.46,4802.73 h60
  text "BOW & TWIST:" at 11408.23,4657.54 h60
  text "X" at 12256.46,4657.54 h60
  text "ANSI IPC-6012 TYPE 3 CLASS 2" at 12434.48,4657.54 h60
  text "OTHER +/-" at 12434.46,4510.85 h60
  text "DRILLING:" at 11333.46,4380.23 h60
  text "NC_DRILL FILES" at 13094.46,4275.04 h60
  text "REFERENCE:" at 11408.23,4271.1 h60
  text "X" at 12065.46,4271.01 h60
  text "AS SHOWN" at 12243.46,4271.1 h60
  text "X" at 12966.46,4271.1 h60
  text "OTHER" at 13392.46,4128.85 h60
  text "PTH COPPER THICKNESS:" at 11407.91,4125.32 h60
  text "X" at 12547.14,4125.32 h60
  text "20-30 um" at 12675.14,4125.32 h60
  text "BOARD FINISH:" at 11333.46,3977.73 h60
  text "SILKSCREEN:" at 11488.68,3867.6 h60
  text "X" at 12446.46,3867.6 h60
  text "TOP" at 12563.46,3867.6 h60
  text "X" at 12956.46,3867.6 h60
  text "BOTTOM" at 13074.46,3867.6 h60
  text "SILKSCREEN COLOR:" at 11488.68,3712.41 h60
  text "X" at 12445.46,3712.41 h60
  text "WHITE" at 12563.46,3712.41 h60
  text "OTHER" at 13074.46,3712.41 h60
  text "X" at 12576.46,3568.96 h60
  text "GREEN" at 12694.46,3568.96 h60
  text "OTHER" at 13312.46,3568.96 h60
  text "SOLDER RESIST COLOR:" at 11488.68,3562.1 h60
  text "X" at 12576.46,3414.71 h60
  text "MATTE" at 12694.46,3414.71 h60
  text "SEMI-GLOSS" at 13312,3414.07 h60
  text "IMMERSION GOLD (ENIG)" at 12394.46,3241.94 h60
  text "ENEPIG" at 13732,3234.72 h60
  text "SURFACE FINISH:" at 11333.46,3233.72 h60
  text "X" at 12216.46,3233.72 h60
  text "IMM. TIN/SILVER OR EQUIV" at 11663,3096.4 h60
  text "OTHER" at 13094.46,3092.47 h60
  text "ARRAY/PANEL:" at 11333.46,2937.09 h60
  text "CUT AND TRIM PER M1 BOARD OUTLINE" at 12394.46,2928.87 h60
  text "N.C. ROUTE" at 12394.46,2792.9 h60
  text "X" at 13082.46,2792.9 h60
  text "V. SCORE" at 13260.46,2792.9 h60
  text "CERTIFICATION:" at 11333.46,2663.77 h60
  text "MATERIALS AND WORKMANSHIP FOR ALL PCBS" at 12058.46,2663.77 h60
  text "TO MEET OR EXCEED THE REQUIREMENTS OF:" at 12058.46,2569.71 h60
  text "X" at 11695.97,2441.08 h60
  text "ANSI IPC-A-600F CLASS ->" at 11823.96,2441.08 h60
  text "X" at 13471.97,2441.08 h60
  text "2" at 13581.96,2441.08 h60
  text "1" at 13266.96,2439.58 h60
  text "3" at 13935.96,2439.58 h60
  text "X" at 12507.97,2293.39 h60
  text "RoHS" at 12635.96,2293.39 h60
  text "OTHER" at 13280.36,2293.39 h60
  text "PER ORDER" at 13677.42,2293.39 h60
  text "ALL BOARDS MUST MEET OR EXCEED UL94-V0 REQUIREMENTS." at 11361,2139.57 h60
  text "PCB MUST BEAR THE UL94V-0 UL REGISTERED MATERIAL ID NUMBER" at 11361,2023.5 h60
  text "ADDITIONAL REQUIREMENTS:" at 11333.46,1854.08 h60
  text "MICROSECTION:" at 11408.23,1746.95 h60
  text "YES" at 12313.96,1746.95 h60
  text "REQUIRED" at 13175.46,1602.62 h60
  text "BARE BOARD ELEC. TEST:" at 11408.23,1599.76 h60
  text "NONE" at 12713.96,1599.76 h60
  text "X" at 13057.46,1599.76 h60
  text "PER ORDER" at 13767.46,1599.76 h60
  text "XX MIL VIAS REQUIRE NON-CONDUCTIVE FILL AND PLANARIZE" at 11576.38,1394.82 h59
  text "XX MIL VIAS REQUIRE CONDUCTIVE FILL AND PLANARIZE" at 11584.38,1290.84 h60
  text "OUTER XX MIL TRACES REQUIRE 50 OHM SINGLE-ENDED IMPEDANCE" at 11583.39,1127.46 h58
  text "LAYER 2 & 3 (INNER LAYERS) XX MIL WIDE, XX MIL SPACE / TRACES REQUIRE 100 OHM DIFFERENTIAL IMPEDANCE" at 11575.39,891.74 h60
  text ".Layer_Name" at 577,-858.49 h60
M11 Gerber Information:
  lines w10: -292,-930.17 6308,-930.17 ; -292,-726.83 6310,-726.83 ; -292,-523.5 -292,-1133.5 3713,-1133.5 6310,-1133.5 6310,-523.5 -291.5,-523.5 -291.5,-1133.5 1284,-1133.5 ; 2173,-1133.5 2173,-523.5 ; 3440,-726.83 3440,-523.5 ; 4280,-726.83 4280,-523.5 ; 4902,-1140 4902,-937.17
  text "ALL ARTWORK VIEWED FROM TOP SIDE" at -228.5,-655.67 h60
  text "BOARD #:" at 2248,-655.67 h60
  text ".PRJ_Number" at 2793.5,-655.67 h60
  text "REV:" at 3638,-655.67 h60
  text ".PCB_Rev" at 3929.5,-655.67 h60
  text "SVN REV:" at 4476,-655.67 h60
  text ".VersionControl_RevNumber" at 4982,-655.67 h60
  text "LAYER NAME =" at -228.5,-858.49 h60
  text "TID #:" at 2248,-859 h60
  text ".TID" at 2793.5,-859 h60
  text "PLOT NAME =" at -228.5,-1064.34 h60
  text ".plot_File_Name" at 577,-1064.34 h60
  text "GENERATED    :" at 2250,-1064.34 h60
  text ".Print_Date" at 3119.5,-1064.34 h60
  text ".Print_Time" at 3848.5,-1064.34 h60
  text "TEXAS INSTRUMENTS" at 5113,-1064.34 h60
M12 Stackup:
  drawing of 191 lines, arcs and shapes, not listed
  text "Layer" at 6720.09,7290 h60
  text "Name" at 7130,7290 h60
  text "Material" at 8059.74,7290 h60
  text "Thickness" at 8919.51,7290 h60
  text "Constant" at 9569.35,7290 h60
  text "Board Layer Stack" at 10139.21,7290 h60
  text "1" at 6720.09,7170 h60
  text "Top Overlay" at 7130,7170 h60
  text "2" at 6720.09,7050 h60
  text "Top Solder" at 7130,7050 h60
  text "Solder Resist" at 8059.74,7050 h60
  text "0.40mil" at 8919.51,7050 h60
  text "3.5" at 9569.35,7050 h60
  text "3" at 6720.09,6930 h60
  text "Top Layer" at 7130,6930 h60
  text "Copper" at 8059.74,6930 h60
  text "1.40mil" at 8919.51,6930 h60
  text "4" at 6720.09,6810 h60
  text "Dielectric 2" at 7130,6810 h60
  text "FR-4" at 8059.74,6810 h60
  text "59.20mil" at 8919.51,6810 h60
  text "4.2" at 9569.35,6810 h60
  text "5" at 6720.09,6690 h60
  text "Bottom Layer" at 7130,6690 h60
  text "Copper" at 8059.74,6690 h60
  text "1.40mil" at 8919.51,6690 h60
  text "6" at 6720.09,6570 h60
  text "Bottom Solder" at 7130,6570 h60
  text "Solder Resist" at 8059.74,6570 h60
  text "0.40mil" at 8919.51,6570 h60
  text "3.5" at 9569.35,6570 h60
  text "7" at 6720.09,6450 h60
  text "Bottom Overlay" at 7130,6450 h60
  text ".Layer_Name" at 577,-858.49 h60
M13 Component Bodies Top:
  text ".Layer_Name" at 577,-858.49 h60
M14 Component Bodies Bottom:
  text ".Layer_Name" at 577,-858.49 h60
M15 Courtyards Top:
  text ".Layer_Name" at 577,-858.49 h60
M16 Courtyards Bottom:
  text ".Layer_Name" at 577,-858.49 h60
Drill Drawing:
  circle w10: c880.62,5975.83 r33.33
  lines w10: 847.29,6092.5 913.96,6092.5 913.96,6159.17 847.29,6159.17 847.29,6092.5
  lines w15: 787.5,5897.5 11198.62,5897.5 ; 787.5,6197.5 11198.62,6197.5 ; 1338.38,5747.5 1338.38,6347.5 ; 1818.26,5747.5 1818.26,6347.5 ; 2907.94,5747.5 2907.94,6347.5 ; 3413.81,5747.5 3413.81,6347.5 ; 4147.62,5747.5 4147.62,6347.5 ; 5647.17,5747.5 5647.17,6347.5 ; 6237.02,5747.5 6237.02,6347.5 ; 6982.81,5747.5 6982.81,6347.5 ; 7632.64,5747.5 7632.64,6347.5 ; 8486.41,5747.5 8486.41,6347.5 ; 9820.01,5747.5 9820.01,6347.5 ; 787.5,5747.5 11198.62,5747.5 11198.62,6347.5 787.5,6347.5 787.5,5747.5
  text "Symbol" at 877.5,6242.5 h72
  text "Count" at 1383.38,6242.5 h72
  text "Hole Size" at 1863.26,6242.5 h72
  text "Plated" at 2952.94,6242.5 h72
  text "Hole Type" at 3458.81,6242.5 h72
  text "Drill Layer Pair" at 4192.62,6242.5 h72
  text "Via/Pad" at 5692.17,6242.5 h72
  text "Pad Shape" at 6282.02,6242.5 h72
  text "Template" at 7027.81,6242.5 h72
  text "Description" at 7677.64,6242.5 h72
  text "Hole Tolerance (+)" at 8531.41,6242.5 h72
  text "Hole Tolerance (-)" at 9865.01,6242.5 h72
  text "2" at 1383.38,6092.5 h60
  text "10.00mil (0.254mm)" at 1863.26,6092.5 h60
  text "PTH" at 2952.94,6092.5 h60
  text "Round" at 3458.81,6092.5 h60
  text "Top Layer - Bottom Layer" at 4192.62,6092.5 h60
  text "Via" at 5692.17,6092.5 h60
  text "Rounded" at 6282.02,6092.5 h60
  text "v51h25" at 7027.81,6092.5 h60
  text "7" at 1383.38,5942.5 h60
  text "27.99mil (0.711mm)" at 1863.26,5942.5 h60
  text "PTH" at 2952.94,5942.5 h60
  text "Round" at 3458.81,5942.5 h60
  text "Top Layer - Bottom Layer" at 4192.62,5942.5 h60
  text "Pad" at 5692.17,5942.5 h60
  text "(Mixed)" at 6282.02,5942.5 h60
  text "(Mixed)" at 7027.81,5942.5 h60
  text "9 Total" at 1383.38,5792.5 h60
  text ".Layer_Name" at 577,-858.49 h60
M17 Embedded Cavity:
  text ".Layer_Name" at 577,-858.49 h60
M18 Embedded Assembly:
  text ".Layer_Name" at 577,-858.49 h60
M19 Embedded Keepout:
  text ".Layer_Name" at 577,-858.49 h60

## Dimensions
600,595 to 600,1245 on M2 Board Dimensions
600,595 to 1600,595 on M2 Board Dimensions
0,-400 to 1000,-400 on M2 Board Dimensions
